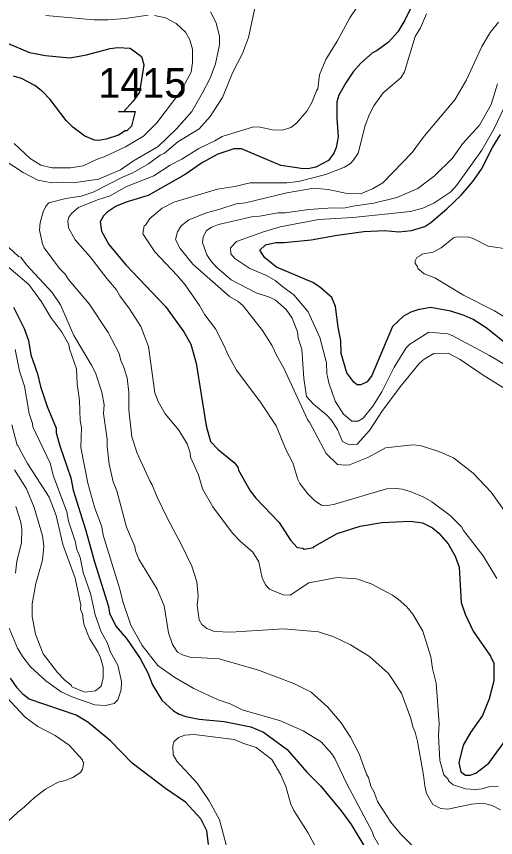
# Model space of a CAD drawing. Extents: x 598.3 to 623.2, y 6902.2 to 6930.1.
# Drawn here: x 608.794 to 610.086, y 6915.946 to 6918.158 of the extents above; entities that cross this region are included whole.
import ezdxf

# ---------------------------------------------------------------- set-up
doc = ezdxf.new("R2010")
doc.units = 0
doc.header["$LTSCALE"] = 0.032
doc.layers.add('1', color=7, linetype='Continuous', lineweight=25)
doc.layers.add('2', color=7, linetype='Continuous', lineweight=13)
doc.layers.add('21', color=7, linetype='Continuous')

msp = doc.modelspace()

# ---------------------------------------------------------------- linework, layer by layer
at = {"layer": '1'}
for points in [[(609.8557, 6918.1771), (609.8418, 6918.1477), (609.8229, 6918.1169), (609.7972, 6918.0885), (609.7664, 6918.066), (609.7538, 6918.0597), (609.723, 6918.0321), (609.7025, 6918.0084), (609.6824, 6917.9795), (609.6632, 6917.9458), (609.6582, 6917.928), (609.6581, 6917.8827), (609.6614, 6917.8335)], [(608.7653, 6918.088), (608.8294, 6918.0608), (608.8729, 6918.0523), (608.9377, 6918.0468), (608.9831, 6918.0542), (609.047, 6918.0718), (609.0678, 6918.0742), (609.1007, 6918.0724), (609.1311, 6918.05), (609.1377, 6918.0275), (609.1261, 6917.9542), (609.1087, 6917.9296), (609.0828, 6917.9006), (609.0693, 6917.9018), (609.1146, 6917.9016), (609.1046, 6917.8626), (609.0921, 6917.8499), (609.0869, 6917.8496), (609.0691, 6917.8379), (609.0357, 6917.8273), (609.0166, 6917.8242), (609.0043, 6917.825), (608.9784, 6917.8358), (608.9464, 6917.8594), (608.9282, 6917.8773), (608.8848, 6917.9345), (608.8655, 6917.9546), (608.8435, 6917.9716), (608.8077, 6917.9907), (608.7864, 6917.9973)], [(610.1186, 6917.2738), (610.0611, 6917.3192), (610.0252, 6917.3415), (610.0015, 6917.3525), (609.9653, 6917.3643), (609.9102, 6917.374), (609.8766, 6917.3681), (609.8572, 6917.3614), (609.8374, 6917.3508), (609.8077, 6917.3224), (609.752, 6917.1909), (609.7401, 6917.1738), (609.7224, 6917.1654), (609.7127, 6917.1661), (609.704, 6917.1729), (609.685, 6917.1983), (609.6695, 6917.2497), (609.6687, 6917.285), (609.6614, 6917.3209), (609.6542, 6917.377), (609.6445, 6917.4013), (609.611, 6917.43), (609.5929, 6917.4411), (609.4953, 6917.4827), (609.4642, 6917.5074), (609.4503, 6917.5288), (609.4658, 6917.5425), (609.4935, 6917.5489), (609.5157, 6917.5491), (609.5884, 6917.5564), (609.6593, 6917.5692), (609.7311, 6917.5788), (609.7872, 6917.5812), (609.8248, 6917.5781), (609.8594, 6917.5812), (609.8954, 6917.5919), (609.9113, 6917.6028), (609.9547, 6917.6398), (609.9931, 6917.6765), (610.0245, 6917.7138), (610.0484, 6917.7468), (610.0782, 6917.8045), (610.0997, 6917.8397)], [(609.6614, 6917.8335), (609.6558, 6917.805), (609.6501, 6917.7901), (609.6355, 6917.7699), (609.6013, 6917.7524), (609.5842, 6917.748), (609.568, 6917.7473), (609.5071, 6917.7561), (609.4007, 6917.8014), (609.3802, 6917.8014), (609.3374, 6917.7872), (609.2958, 6917.7644), (609.2489, 6917.7323), (609.1493, 6917.6753), (609.0926, 6917.6589), (609.0627, 6917.6465), (609.0387, 6917.6304), (609.0291, 6917.6207), (609.0195, 6917.6046), (609.0235, 6917.5797), (609.0434, 6917.5435), (609.0893, 6917.4887), (609.1958, 6917.3765), (609.2452, 6917.3087), (609.2646, 6917.2748), (609.2788, 6917.2239), (609.306, 6917.0551), (609.3178, 6917.0134), (609.3382, 6916.9914), (609.3815, 6916.9561), (609.3908, 6916.9436), (609.3928, 6916.9359), (609.4244, 6916.8806), (609.4398, 6916.8605), (609.5025, 6916.7947), (609.5331, 6916.7475), (609.5513, 6916.7274), (609.566, 6916.7257), (609.5697, 6916.7232), (609.5947, 6916.7273), (609.5969, 6916.7306), (609.6593, 6916.7654), (609.7208, 6916.7848), (609.7791, 6916.7945), (609.8569, 6916.7985), (609.8886, 6916.7937), (609.916, 6916.7808), (609.9331, 6916.7664), (609.9585, 6916.7378), (609.977, 6916.7041), (609.9876, 6916.6747), (609.9934, 6916.5792), (610.0045, 6916.5481), (610.0252, 6916.5024), (610.0728, 6916.4348), (610.0816, 6916.416), (610.0815, 6916.3684), (610.0686, 6916.3198), (610.051, 6916.2751), (610.0188, 6916.2296), (609.9987, 6916.1955), (609.9869, 6916.1472), (609.992, 6916.1231), (610.0049, 6916.1147), (610.0176, 6916.1146), (610.0328, 6916.12), (610.0675, 6916.1466), (610.1208, 6916.2195)], [(608.7859, 6917.3751), (608.8146, 6917.3177), (608.8264, 6917.2847), (608.8329, 6917.2465), (608.8509, 6917.195), (608.859, 6917.161), (608.8769, 6917.1072), (608.9013, 6917.0494), (608.9015, 6917.0363), (608.911, 6917.0017), (608.9408, 6916.915), (608.9467, 6916.8816), (608.98, 6916.776), (609.0042, 6916.6889), (609.0427, 6916.5685), (609.0454, 6916.5503), (609.0624, 6916.516), (609.0909, 6916.4826), (609.1279, 6916.4289), (609.148, 6916.3901), (609.1611, 6916.3573), (609.1863, 6916.3159), (609.2178, 6916.2878), (609.233, 6916.279), (609.2507, 6916.2724), (609.2866, 6916.265), (609.3543, 6916.2586), (609.4262, 6916.2447), (609.4599, 6916.2302), (609.5241, 6916.183), (609.5767, 6916.1223), (609.6142, 6916.0856), (609.6699, 6916.018), (609.6964, 6915.9815), (609.7415, 6915.9072)], [(609.3116, 6915.928), (609.3076, 6915.9647), (609.2915, 6915.9963), (609.2497, 6916.0414), (609.1959, 6916.0781), (609.1064, 6916.1467), (609.0476, 6916.207), (608.9862, 6916.2575), (608.9549, 6916.2762), (608.8287, 6916.3192), (608.812, 6916.3317), (608.7957, 6916.3493), (608.7785, 6916.3757)]]:
    msp.add_lwpolyline(points, dxfattribs=at)
at = {"layer": '2'}
for points in [[(609.4396, 6918.1925), (609.4203, 6918.1013), (609.4038, 6918.0584), (609.3767, 6918.006), (609.35, 6917.9397), (609.3166, 6917.888), (609.287, 6917.8556), (609.2295, 6917.8205), (609.1936, 6917.79), (609.182, 6917.7846), (609.1501, 6917.7606), (609.1083, 6917.7366), (609.08, 6917.7248), (609.0007, 6917.6842), (608.9684, 6917.6741), (608.9272, 6917.6676), (608.8817, 6917.6555), (608.8737, 6917.6466), (608.8658, 6917.6317), (608.8585, 6917.6029), (608.8561, 6917.5822), (608.8641, 6917.5459), (608.8691, 6917.5351), (608.9106, 6917.479), (608.9258, 6917.4637), (608.9349, 6917.4496), (608.9905, 6917.3835), (609.0412, 6917.3063), (609.0712, 6917.2497), (609.0753, 6917.231), (609.0827, 6917.2152), (609.0924, 6917.1841), (609.0972, 6917.1452), (609.0973, 6917.0986), (609.1054, 6917.0258), (609.1201, 6916.9817), (609.1536, 6916.9068), (609.1602, 6916.8967), (609.1732, 6916.8627), (609.2011, 6916.8053), (609.2395, 6916.7348), (609.2668, 6916.6769), (609.2802, 6916.6353), (609.2842, 6916.5959), (609.2817, 6916.5721), (609.2866, 6916.5325), (609.2938, 6916.52), (609.3073, 6916.509), (609.3285, 6916.5015), (609.3725, 6916.4991), (609.5138, 6916.5088), (609.6086, 6916.5007), (609.6499, 6916.4866), (609.6949, 6916.4657), (609.7462, 6916.4336), (609.797, 6916.3877), (609.8321, 6916.335), (609.858, 6916.267), (609.8628, 6916.2446), (609.8694, 6916.23), (609.8759, 6916.2051), (609.8921, 6916.1145), (609.895, 6916.0852), (609.9001, 6916.0649), (609.9167, 6916.035), (609.9386, 6916.0247), (609.9575, 6916.0231), (610.0211, 6916.0361), (610.0521, 6916.0392), (610.0767, 6916.0327), (610.0991, 6916.0207)], [(609.3177, 6918.1702), (609.3323, 6918.1405), (609.3417, 6918.104), (609.3418, 6918.0813), (609.3309, 6918.0304), (609.3161, 6917.9918), (609.2962, 6917.9518), (609.2667, 6917.9023), (609.2257, 6917.8555), (609.1767, 6917.8073), (609.11, 6917.7689), (609.0747, 6917.7449), (609.0154, 6917.7195), (608.9472, 6917.71), (608.9204, 6917.7117), (608.8898, 6917.71), (608.8514, 6917.7172), (608.8119, 6917.738), (608.7331, 6917.7892)], [(610.0929, 6916.0845), (610.0708, 6916.0838), (610.0499, 6916.0778), (610.0321, 6916.0757), (610.0052, 6916.0773), (609.9718, 6916.0883), (609.9591, 6916.0993), (609.9583, 6916.1033), (609.9469, 6916.1151), (609.9355, 6916.1539), (609.9326, 6916.2214), (609.9342, 6916.2527), (609.9262, 6916.3617), (609.9162, 6916.4019), (609.9115, 6916.4334), (609.89, 6916.5025), (609.8629, 6916.5484), (609.8464, 6916.5675), (609.8237, 6916.5884), (609.8082, 6916.5992), (609.7502, 6916.6299), (609.7108, 6916.643), (609.6588, 6916.6463), (609.5822, 6916.6325), (609.5325, 6916.5994), (609.5131, 6916.6003), (609.4768, 6916.6156), (609.4659, 6916.6273), (609.457, 6916.6454), (609.4478, 6916.689), (609.4313, 6916.7153), (609.3973, 6916.7444), (609.3767, 6916.7659), (609.3238, 6916.8373), (609.2961, 6916.8857), (609.2846, 6916.9231), (609.2638, 6916.9706), (609.263, 6916.9828), (609.2541, 6917.0068), (609.2317, 6917.0436), (609.195, 6917.0879), (609.1763, 6917.1204), (609.1669, 6917.1439), (609.1506, 6917.2688), (609.1294, 6917.3225), (609.0992, 6917.3704), (609.0728, 6917.4051), (609.0642, 6917.4218), (609.0377, 6917.4523), (608.9929, 6917.5106), (608.9525, 6917.5561), (608.9347, 6917.589), (608.9329, 6917.6075), (608.9355, 6917.617), (608.9431, 6917.6278), (608.9617, 6917.6431), (609.0124, 6917.6642), (609.0468, 6917.6751), (609.0891, 6917.6994), (609.1648, 6917.7288), (609.2087, 6917.7576), (609.2403, 6917.7738), (609.286, 6917.8026), (609.3293, 6917.8227), (609.349, 6917.835), (609.4337, 6917.8605), (609.4516, 6917.8598), (609.485, 6917.8523), (609.5111, 6917.8513), (609.5344, 6917.8589), (609.5497, 6917.8702), (609.5774, 6917.9026), (609.5909, 6917.9258), (609.6029, 6917.9578), (609.6071, 6917.9634), (609.6113, 6918.0009), (609.6287, 6918.042), (609.6588, 6918.091), (609.6928, 6918.1542), (609.7118, 6918.1821)], [(609.1666, 6918.1609), (609.1958, 6918.1544), (609.2251, 6918.139), (609.2504, 6918.1153), (609.2621, 6918.0951), (609.2688, 6918.0702), (609.2688, 6918.0341), (609.2655, 6918.0082), (609.2377, 6917.9564), (609.1729, 6917.8717), (609.1368, 6917.8357), (609.0881, 6917.8066), (609.0307, 6917.7794), (609.0098, 6917.7723), (608.9739, 6917.7554), (608.9395, 6917.7505), (608.8895, 6917.7505), (608.8602, 6917.7574), (608.8314, 6917.7751), (608.7877, 6917.8156)], [(608.8732, 6918.1607), (609.0028, 6918.1488), (609.0415, 6918.1488), (609.0871, 6918.1523), (609.1496, 6918.1617)], [(609.2873, 6917.3792), (609.2487, 6917.4354), (609.2279, 6917.4603), (609.1669, 6917.5236), (609.1353, 6917.5724), (609.1389, 6917.5944), (609.1425, 6917.5961), (609.1542, 6917.6139), (609.1873, 6917.6413), (609.2186, 6917.6581), (609.3362, 6917.6928), (609.3827, 6917.7003), (609.4242, 6917.7099), (609.5236, 6917.71), (609.5545, 6917.7138), (609.6288, 6917.7323), (609.6783, 6917.7519), (609.6948, 6917.762), (609.7025, 6917.7696), (609.7156, 6917.7901), (609.7343, 6917.864), (609.7462, 6917.8949), (609.7582, 6917.9175), (609.7828, 6917.952), (609.831, 6917.9929), (609.8405, 6918.009), (609.8696, 6918.1042), (609.8835, 6918.1275), (609.9, 6918.1652)], [(610.094, 6918.1424), (610.0712, 6918.1146), (610.0486, 6918.0773), (610.0077, 6917.9874), (609.9759, 6917.9331), (609.8933, 6917.8359), (609.8612, 6917.7915), (609.7819, 6917.7096), (609.754, 6917.6936), (609.7221, 6917.6801), (609.6859, 6917.6807), (609.635, 6917.6921), (609.5961, 6917.6954), (609.5228, 6917.6832), (609.412, 6917.6563), (609.387, 6917.6533), (609.3429, 6917.6384), (609.3069, 6917.6293), (609.2589, 6917.6103), (609.2385, 6917.5938), (609.2282, 6917.5778), (609.2226, 6917.5574), (609.2358, 6917.5325), (609.2698, 6917.4904), (609.3683, 6917.4034), (609.3917, 6917.3904), (609.4052, 6917.3786), (609.4578, 6917.3121), (609.484, 6917.2707), (609.4949, 6917.2456), (609.5148, 6917.2108), (609.5794, 6917.0703), (609.5846, 6917.0654), (609.6297, 6916.9809), (609.6601, 6916.9507), (609.6813, 6916.949)], [(610.1523, 6917.1298), (610.0522, 6917.1913), (609.9907, 6917.2342), (609.9579, 6917.2509), (609.9197, 6917.2502), (609.8932, 6917.2352), (609.8811, 6917.2236), (609.8291, 6917.1606), (609.7792, 6917.0939), (609.7465, 6917.0428), (609.713, 6917.0055), (609.6912, 6917.0042), (609.6734, 6917.0127), (609.6596, 6917.0457), (609.643, 6917.0711), (609.6312, 6917.0844), (609.5949, 6917.1134), (609.5765, 6917.1346), (609.5692, 6917.1825), (609.5634, 6917.2621), (609.5538, 6917.2913), (609.552, 6917.3083), (609.5374, 6917.3452), (609.5215, 6917.369), (609.4925, 6917.3937), (609.4766, 6917.4016), (609.4402, 6917.4131), (609.3733, 6917.4489), (609.334, 6917.483), (609.3184, 6917.4996), (609.3079, 6917.516), (609.2956, 6917.5487), (609.2978, 6917.5647), (609.3069, 6917.5812), (609.3214, 6917.5905), (609.3387, 6917.5975), (609.4321, 6917.6193), (609.4491, 6917.6202), (609.5001, 6917.629), (609.5187, 6917.6291), (609.5824, 6917.6379), (609.6464, 6917.6421), (609.6772, 6917.6412), (609.7011, 6917.6468), (609.7575, 6917.6549), (609.8196, 6917.6704), (609.8762, 6917.6949), (609.9213, 6917.7286), (609.97, 6917.7766), (609.9966, 6917.8144), (610.0426, 6917.8647), (610.0738, 6917.9205), (610.0913, 6917.9766)], [(610.1648, 6917.1883), (610.07, 6917.2447), (609.9688, 6917.2985), (609.9569, 6917.3028), (609.9065, 6917.3075), (609.8552, 6917.2754), (609.8451, 6917.2655), (609.8126, 6917.2136), (609.7791, 6917.1464), (609.7552, 6917.1084), (609.7291, 6917.0755), (609.7156, 6917.0681), (609.6981, 6917.068), (609.6756, 6917.087), (609.6539, 6917.1221), (609.6368, 6917.1711), (609.6315, 6917.1958), (609.6298, 6917.2251), (609.6121, 6917.2929), (609.5804, 6917.3627), (609.5421, 6917.4084), (609.5126, 6917.4292), (609.492, 6917.4471), (609.4685, 6917.4604), (609.4232, 6917.479), (609.3826, 6917.5056), (609.3725, 6917.5183), (609.3709, 6917.5349), (609.3875, 6917.5518), (609.4605, 6917.5782), (609.505, 6917.5909), (609.6098, 6917.6112), (609.7016, 6917.6164), (609.8571, 6917.6323), (609.8895, 6917.6417), (609.9199, 6917.6546), (609.965, 6917.6859), (609.9807, 6917.703), (610.049, 6917.798), (610.081, 6917.8539), (610.1201, 6917.9353)], [(610.1284, 6917.5303), (610.0659, 6917.539), (610.0252, 6917.5601), (610.0141, 6917.5633), (609.9806, 6917.5643), (609.9729, 6917.5616), (609.9389, 6917.535), (609.9177, 6917.523), (609.8859, 6917.5173), (609.8851, 6917.5146), (609.874, 6917.5087), (609.8694, 6917.5001), (609.8688, 6917.4924), (609.8757, 6917.4842), (609.8765, 6917.4786), (609.8931, 6917.4648), (609.9227, 6917.4535), (609.9997, 6917.4069), (610.083, 6917.3653), (610.1641, 6917.3159)], [(608.7729, 6917.5366), (608.8001, 6917.5116), (608.8063, 6917.5094), (608.8211, 6917.4889), (608.8909, 6917.4143), (608.9125, 6917.3808), (608.9489, 6917.2982), (608.9967, 6917.2189), (609.0069, 6917.1983), (609.0243, 6917.1458), (609.0308, 6917.1115), (609.0293, 6917.0889), (609.0389, 6917.0195), (609.0387, 6916.9994), (609.0446, 6916.9518), (609.0547, 6916.9044), (609.0649, 6916.8801), (609.0909, 6916.7825), (609.1133, 6916.73), (609.115, 6916.7187), (609.1246, 6916.696), (609.1732, 6916.615), (609.1925, 6916.57), (609.2041, 6916.498), (609.2151, 6916.4664), (609.2285, 6916.4456), (609.2419, 6916.438), (609.2613, 6916.4318), (609.3406, 6916.4276), (609.4467, 6916.3971), (609.5419, 6916.3616), (609.5891, 6916.3381), (609.6334, 6916.2979), (609.6694, 6916.2556), (609.6948, 6916.2163)], [(608.7736, 6917.4818), (608.8272, 6917.4361), (608.8613, 6917.3892), (608.8869, 6917.3474), (608.9168, 6917.3075), (608.9352, 6917.274), (608.9369, 6917.2626), (608.9563, 6917.2089), (608.958, 6917.1682), (608.9644, 6917.1231), (608.9661, 6917.0692), (608.9693, 6917.0505), (608.9677, 6916.9966), (608.9862, 6916.9004), (609.0046, 6916.8359), (609.0244, 6916.7829), (609.0282, 6916.7612), (609.0729, 6916.615), (609.0807, 6916.5817), (609.1028, 6916.5179), (609.1327, 6916.4632), (609.1754, 6916.4095), (609.2211, 6916.3772), (609.2723, 6916.3475), (609.3384, 6916.3175), (609.3703, 6916.3066), (609.4026, 6916.2906), (609.5063, 6916.2609), (609.567, 6916.2341), (609.6159, 6916.2045), (609.6445, 6916.172), (609.6527, 6916.1596), (609.6843, 6916.0929), (609.7544, 6915.961), (609.7572, 6915.9505), (609.7705, 6915.9273)], [(610.0895, 6916.6442), (610.0526, 6916.7052), (610, 6916.7732), (609.9945, 6916.7836), (609.9637, 6916.8137), (609.9143, 6916.8507), (609.8908, 6916.8639), (609.8555, 6916.8782), (609.8341, 6916.8843), (609.8112, 6916.8875), (609.7917, 6916.8859), (609.6528, 6916.8439), (609.6337, 6916.8407), (609.6169, 6916.8417), (609.5985, 6916.853), (609.5796, 6916.8721), (609.5581, 6916.9), (609.5526, 6916.911), (609.5395, 6916.9554), (609.521, 6916.9893), (609.4945, 6917.0554), (609.4543, 6917.1164), (609.3876, 6917.2048), (609.3638, 6917.2473), (609.3545, 6917.2707), (609.331, 6917.3161), (609.3019, 6917.3541), (609.2873, 6917.3792)], [(608.7904, 6917.261), (608.8021, 6917.2023), (608.8156, 6917.1618), (608.8282, 6917.0884), (608.8373, 6917.0616), (608.8381, 6917.0522), (608.8852, 6916.9545), (608.894, 6916.9198), (608.9296, 6916.8239), (608.9344, 6916.7983), (608.9538, 6916.7416), (608.9563, 6916.7248), (608.966, 6916.7005), (608.9742, 6916.6599), (608.9936, 6916.6032), (609.0066, 6916.5465), (609.0225, 6916.5004), (609.0388, 6916.4718), (609.0476, 6916.4452), (609.0671, 6916.411), (609.0777, 6916.367), (609.0762, 6916.3438), (609.0679, 6916.3168), (609.0577, 6916.3073), (609.0347, 6916.3023), (609.0052, 6916.3039), (608.9458, 6916.3245), (608.9143, 6916.3387), (608.8735, 6916.3688), (608.8321, 6916.4064), (608.8116, 6916.4326), (608.7966, 6916.4566), (608.7749, 6916.5101)], [(608.7816, 6917.0581), (608.7961, 6917.0028), (608.7992, 6917.0017), (608.8038, 6916.9895), (608.8243, 6916.9534), (608.8825, 6916.8627), (608.9013, 6916.8139), (608.9192, 6916.736), (608.9523, 6916.6445), (608.9676, 6916.5726), (608.9669, 6916.5616), (608.9725, 6916.5481), (608.9756, 6916.5214), (608.991, 6916.4823), (609.0137, 6916.4467), (609.0212, 6916.43), (609.0276, 6916.4054), (609.0284, 6916.3766), (609.0225, 6916.354), (609.0071, 6916.3415), (608.9785, 6916.338), (608.9432, 6916.3521), (608.9426, 6916.3555), (608.9235, 6916.3708), (608.9048, 6916.3911), (608.8666, 6916.4413), (608.8453, 6916.4939), (608.8366, 6916.5419), (608.8365, 6916.5755), (608.8462, 6916.6309), (608.8641, 6916.6931), (608.8681, 6916.7308), (608.8647, 6916.7594), (608.8418, 6916.8356), (608.821, 6916.8854), (608.7887, 6916.9369)], [(609.6813, 6916.949), (609.6921, 6916.9504), (609.7414, 6916.9701), (609.7889, 6916.9956), (609.8619, 6917.0042), (609.8824, 6917.0025), (609.9335, 6916.986), (609.9726, 6916.9688), (610.0254, 6916.9276), (610.0744, 6916.8768), (610.109, 6916.8268)], [(608.7912, 6916.6585), (608.7952, 6916.6906), (608.8075, 6916.74), (608.809, 6916.7769), (608.8058, 6916.7959), (608.7929, 6916.838)], [(608.6867, 6915.9122), (608.7967, 6916.0139), (608.8163, 6916.0288), (608.8428, 6916.0544), (608.8722, 6916.0764), (608.9063, 6916.0958), (608.9252, 6916.0996), (608.946, 6916.1076), (608.9669, 6916.1212), (608.9726, 6916.1304), (608.9757, 6916.149), (608.9726, 6916.1511), (608.9725, 6916.1556), (608.9361, 6916.1953), (608.8984, 6916.2212), (608.8517, 6916.2455), (608.8177, 6916.2708), (608.7425, 6916.35), (608.7163, 6916.3888), (608.7021, 6916.426), (608.6974, 6916.4478), (608.6957, 6916.4707), (608.6834, 6916.5316)], [(609.3594, 6915.9267), (609.342, 6915.9938), (609.314, 6916.0451), (609.2811, 6916.0932), (609.2265, 6916.1519), (609.2171, 6916.1693), (609.2154, 6916.1936), (609.2188, 6916.2037), (609.2312, 6916.2162), (609.2481, 6916.2221), (609.2731, 6916.2238), (609.3808, 6916.2108), (609.4048, 6916.2003), (609.4407, 6916.1888), (609.4825, 6916.1565), (609.5067, 6916.1156), (609.5207, 6916.0838), (609.5339, 6916.0365), (609.5422, 6916.0195), (609.5795, 6915.9601), (609.5974, 6915.9268)], [(609.6948, 6916.2163), (609.7186, 6916.1717), (609.7378, 6916.1172), (609.7432, 6916.1078), (609.7497, 6916.0848), (609.7587, 6916.0685), (609.7674, 6916.0432), (609.8034, 6915.9877), (609.8293, 6915.9564), (609.8985, 6915.8873), (609.9495, 6915.8458), (610.0085, 6915.8072), (610.1598, 6915.7305)]]:
    msp.add_lwpolyline(points, dxfattribs=at)

# ---------------------------------------------------------------- texts
at = {"layer": '21'}
msp.add_text('1415', height=0.08, dxfattribs=at).set_placement((609.0146, 6917.939))

doc.saveas('drawing.dxf')
